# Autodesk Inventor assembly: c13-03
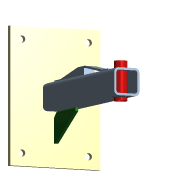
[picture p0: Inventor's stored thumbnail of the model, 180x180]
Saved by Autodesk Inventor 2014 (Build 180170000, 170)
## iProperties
Created: 2011-01
Part Number: c13-03
Document SubType Name: Weldment
Designer: Thom Tremblay
Weld Material: Welded Steel Mild
_SolveAssemblyDoc: Frame Generator Solve Assembly
_Version: 15.0.0
Author: Thom Tremblay
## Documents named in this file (5)
- C:\Inventor 2014 Essentials\Assemblies\Chapter 13\c13-03.iam
- C:\Inventor 2014 Essentials\Parts\Chapter 13\c13-01.ipt
- C:\Inventor 2014 Essentials\Parts\Chapter 13\c13-02.ipt
- C:\Inventor 2014 Essentials\Assemblies\Chapter 13\Frame\Frame c13-01.iam
- C:\Inventor 2014 Essentials\Parts\Chapter 13\c13-03.ipt
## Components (4 placed, 4 different names)
1. c13-01:1 — Mate:2
2. c13-02:1 — Flush:1
3. Frame c13-01:1 [sub-assembly] — Mate:3
4. c13-03:1 — Mate:1, Mate:2, Mate:3
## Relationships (4: Mate 3, Flush 1)
- Flush:1: c13-02:1
- Mate:1: c13-03:1
- Mate:2: c13-01:1 ↔ c13-03:1
- Mate:3: Frame c13-01:1 ↔ c13-03:1
